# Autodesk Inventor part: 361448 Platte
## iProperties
Created: 2006-10
Part Number: 361448 Platte
Material: 1.0332
Description: Platte
Document SubType Name: Modeling
Designer: OSchmidt
Density: 7.84 g/cm^3
Abmessung: St. Bl. 4x1000x2000
HalbzeugNorm: DIN 1542
Zweck: 266482
Author: Natti_01
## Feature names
1. Extrusion3
2. Bohrung1 [Hole]
3. Spiegeln1 [Mirror]
4. Spiegeln2 [Mirror]
5. Bohrung2 [Hole]
6. Rechteckige Anordnung1 [Rectangular Pattern]
7. Bohrung3 [Hole]
8. Rechteckige Anordnung2 [Rectangular Pattern]
